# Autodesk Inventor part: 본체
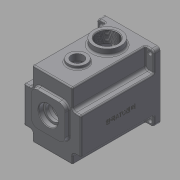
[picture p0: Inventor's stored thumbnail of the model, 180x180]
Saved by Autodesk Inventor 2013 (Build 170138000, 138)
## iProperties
Created: 2016-02
Part Number: 본체
Material: 알루미늄 6061
Document SubType Name: Modeling
Designer: mduedu
Density: 2.71 g/cm^3
Mass: 1353.73 g
Surface Area: 1142.22 cm^2
Volume: 499.53 cm^3
Author: mduedu
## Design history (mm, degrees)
sketch "스케치1"
  geometry: L1 (-47, -47)-(47, -47); L2 (47, -47)-(47, 63); L3 (47, 63)-(-47, 63); L4 (-47, 63)-(-47, -47); 2 further points
  constraints: 8 end point, 2 parallel, 1 horizontal, 1 midpoint, 1 perpendicular, 1 vertical alignment
  dimensions: "d0" = 94 distance of L2.end L3.end; "d155" = 110 distance of L1.end L2.end; "d156" = 47 distance from line of L1 point (0, 0)
extrude "돌출1" new body sketch "스케치1" distance "d2" = 130; taper "d3" = 0 deg
sketch "스케치3"
  geometry: C1 r 40 at (0, 0); 1 further point
  constraints: 1 centre point, 1 coincident
  dimensions: "d9" = 80 diameter of C1
extrude "돌출3" cut sketch "스케치3" distance "d11" = 121; taper "d12" = 0 deg
sketch "스케치4"
  geometry: C1 r 21 at (0, 11); 1 further point
  constraints: 1 centre point, 1 vertical alignment
  dimensions: "d13" = 21 radius of C1; "d15" = 11 distance of point (0, 0) C1.centre
extrude "돌출4" join sketch "스케치4" distance "d16" = 7; taper "d17" = 0 deg
sketch "스케치5"
  geometry: C1 r 15 at (0, -20); 1 further point
  constraints: 1 centre point, 1 vertical alignment
  dimensions: "d18" = 15 radius of C1; "d20" = 20 distance of point (0, 0) C1.centre
extrude "돌출5" join sketch "스케치5" distance "d21" = 7; taper "d22" = 0 deg
sketch "스케치6"
  geometry: L1 (-28, -17)-(28, -17); L2 (28, -17)-(28, 39); L3 (28, 39)-(-28, 39); L4 (-28, 39)-(-28, -17); L5 (-28, -17)-(28, 39); L6 (28, -17)-(-28, 39); C1 r 28 at (0, 11); A1 r 21 centre (0, 11) between (8.978, -7.984) and (-8.978, -7.984) reference; 1 further point
  constraints: 12 end point, 2 midpoint, 2 parallel, 2 tangent, 1 centre point, 1 coincident, 1 horizontal, 1 perpendicular
  dimensions: "d23" = 56 diameter of C1
extrude "돌출6" join sketch "스케치6" distance "d25" = 7; taper "d26" = -3 deg
hole "구멍1" diameter "d29" = 35; stored, may be unused: countersink angle "d33" = 90 deg, drill point angle "d35" = 0 deg; dims "d27" = 10, "d28" = 10, "d30" = 6, "d31" = 4, "d32" = 2, "d34" = 10
hole "구멍2" diameter "d38" = 22; stored, may be unused: countersink angle "d42" = 90 deg, drill point angle "d44" = 0 deg; dims "d36" = 10, "d37" = 10, "d39" = 6, "d40" = 4, "d41" = 2, "d43" = 7
hole "구멍3" diameter "d47" = 19; stored, may be unused: countersink angle "d51" = 90 deg, drill point angle "d53" = 0 deg; dims "d45" = 10, "d46" = 10, "d48" = 6, "d49" = 4, "d50" = 2, "d52" = 1
hole "구멍4" diameter "d56" = 32; stored, may be unused: countersink angle "d60" = 90 deg, drill point angle "d62" = 0 deg; dims "d57" = 6, "d58" = 4, "d59" = 2, "d61" = 8, "d220" = 10, "d221" = 10
hole "구멍5" diameter "d65" = 25; stored, may be unused: countersink angle "d69" = 90 deg, drill point angle "d71" = 0 deg; dims "d63" = 10, "d64" = 10, "d66" = 6, "d67" = 4, "d68" = 2, "d70" = 8
fillet "모깎기2" dims "d73" = 0.3
fillet "모깎기3" dims "d74" = 2
chamfer "모따기1" distance "d75" = 1; stored, may be unused: second distance "d76" = 2, angle "d77" = 45 deg
fillet "모깎기4" dims "d78" = 3
sketch "스케치16"
  geometry: L1 (-23, 32.726)-(23, 32.726); L2 (23, 32.726)-(23, 53); L3 (23, 53)-(-23, 53); L4 (-23, 53)-(-23, 32.726); L5 (-47, 63)-(47, 63) reference; 3 further points
  constraints: 8 end point, 2 parallel, 1 horizontal, 1 midpoint, 1 perpendicular, 1 vertical alignment, 2 other
  dimensions: "d160" = 46 distance of L2.end L3.end; "d163" = 10 distance between parallel lines of L3 L5
extrude "돌출15" cut sketch "스케치16" stored distance "d164" = 10; taper "d165" = 0 deg
fillet "모깎기5" dims "d79" = 2
fillet "모깎기15" dims "d166" = 5
sketch "스케치7"
  geometry: L1 (-23, 48)-(-23, 35.228) reference; L2 (23, 35.228)-(23, 48) reference; L3 (18, 53)-(-18, 53) reference; L4 (47, 63)-(47, -47) reference; L5 (47, -47)-(-47, -47) reference; L6 (-47, -47)-(-47, 63) reference; L7 (-47, 63)-(47, 63) reference; L8 (-26, 48)-(-26, 35.228); L9 (26, 35.228)-(26, 48); L10 (18, 56)-(-18, 56); C1 r 43 at (0, 0); A1 r 5 centre (-18, 48) between (-18, 53) and (-23, 48) reference; A2 r 5 centre (-28, 35.228) between (-24.889, 31.314) and (-23, 35.228) reference; A3 r 40 centre (0, 0) between (-24.889, 31.314) and (24.889, 31.314) reference; A4 r 5 centre (28, 35.228) between (23, 35.228) and (24.889, 31.314) reference; A5 r 5 centre (18, 48) between (23, 48) and (18, 53) reference; A6 r 8 centre (-18, 48) between (-18, 56) and (-26, 48); A7 r 2 centre (-28, 35.228) between (-26.756, 33.662) and (-26, 35.228); A8 r 43 centre (0, 0) between (-26.756, 33.662) and (26.756, 33.662); A9 r 2 centre (28, 35.228) between (26, 35.228) and (26.756, 33.662); A10 r 8 centre (18, 48) between (26, 48) and (18, 56); 1 further point
  constraints: 10 point on circle, 6 centre point, 6 end point, 1 coincident, 7 other
  dimensions: "d80" = 86 diameter of C1; "d167" = 3 distance between parallel lines of L3 L10
extrude "돌출7" cut sketch "스케치7" distance "d83" = 9; taper "d84" = 0 deg
sketch "스케치8" dims "d168" = 36
  geometry: L1 (-36, 4)-(-39.799, 4); L2 (-36, -4)-(-39.799, -4); A1 r 4 centre (-36, 0) between (-36, 4) and (-36, -4); A2 r 40 centre (0, 0) between (-24.889, 31.314) and (24.889, 31.314) reference; A3 r 40 centre (0, 0) between (-39.799, 4) and (-39.799, -4); 2 further points
  constraints: 5 point on circle, 4 end point, 2 centre point, 2 coincident, 2 horizontal alignment, 2 tangent, 1 horizontal, 1 parallel, 2 other
  dimensions: "d169" = 4 radius of A1
extrude "돌출9" join sketch "스케치8" stored distance "d89" = 9; taper "d90" = 0 deg
fillet "모깎기6" dims "d91" = 3.5
node "작업 평면1"
sketch "스케치9"
  geometry: L1 (47, 63)-(33, 63); L2 (33, 63)-(33, 30); L3 (33, 30)-(47, 30); L4 (47, 30)-(47, 63); L5 (47, 63)-(-47, 63) reference; L6 (47, -47)-(47, 63) reference; A1 r 40 centre (0, 0) between (-39.148, -8.214) and (39.148, -8.214) reference; 1 further point
  constraints: 8 end point, 2 parallel, 1 coincident, 1 horizontal, 1 perpendicular
  dimensions: "d95" = 33 distance from line of L2 point (0, 0); "d96" = 30 distance from line of L3 point (0, 0)
extrude "돌출10" cut sketch "스케치9" distance "d97" = 110; taper "d98" = 0 deg
extrude "돌출21" cut sketch "스케치9" stored distance "d217" = 10; taper "d218" = 0 deg
sketch "스케치11" dims "d20" = 20
  geometry: L1 (-40, -40)-(40, -40); L2 (40, -40)-(40, 56); L3 (40, 56)-(-40, 56); L4 (-40, 56)-(-40, -40); L5 (-47, -47)-(47, -47) reference; L6 (47, 63)-(-47, 63) reference; L7 (-47, 63)-(-47, -47) reference; C1 r 3.5 at (-40, 56); C2 r 3.5 at (40, 56); C3 r 3.5 at (40, -40); C4 r 3.5 at (-40, -40); 1 further point
  constraints: 8 end point, 4 centre point, 4 coincident, 3 equal radius, 2 parallel, 1 horizontal, 1 perpendicular
  dimensions: "d109" = 80 distance of L2.end L3.end; "d112" = 7 diameter of C1; "d157" = 7 distance from line of L1.start L5; "d158" = 7 distance between parallel lines of L6 L3; "d159" = 7 distance from line of L7 L3.end
extrude "돌출12" cut sketch "스케치11" stored distance "d113" = 63; taper "d114" = 0 deg
fillet "모깎기7" dims "d115" = 5, "d187" = 5
fillet "모깎기8" dims "d116" = 5
fillet "모깎기18" dims "d219" = 2
fillet "모깎기12" dims "d120" = 2
fillet "모깎기13" dims "d121" = 2
sketch "스케치12"
  geometry: 3 further points
  constraints: 2 horizontal alignment
hole "구멍6" sketch "스케치12" at (36, 0), (-36, 0) diameter "d122" = 3.242; stored, may be unused: countersink angle "d126" = 90 deg, drill point angle "d128" = 120 deg; dims "d123" = 7, "d124" = 4, "d125" = 2, "d127" = 9
fillet "모깎기14" dims "d147" = 10
chamfer "모따기4" distance "d151" = 1; stored, may be unused: second distance "d152" = 2, angle "d153" = 45 deg
sketch "스케치20"
  geometry: L1 (73, -12)-(73, -130) reference; L2 (84, -8)-(77, -8) reference; L3 (84, 0)-(84, -8) reference; L4 (84, 0)-(0, 0) reference; L5 (7, -8)-(0, -8) reference; L6 (11, -130)-(11, -12) reference; L7 (0, -8)-(0, 0) reference; L8 (73, -130)-(11, -130) reference; L9 (42, 0)-(42, -130); C1 r 10 at (42, -89); A1 r 4 centre (77, -12) between (77, -8) and (73, -12) reference; A2 r 4 centre (7, -12) between (11, -12) and (7, -8) reference
  constraints: 2 end point, 1 centre point, 1 midpoint, 1 point on line
  dimensions: "d189" = 20 diameter of C1; "d190" = 41 distance from line of C1.centre L8
extrude "돌출19" cut sketch "스케치20" stored distance "d191" = 10; taper "d192" = 0 deg
sketch "스케치18"
  geometry: C1 r 15 at (42, -89); C2 r 10 at (42, -89) reference; 1 further point
  constraints: 1 centre point, 1 concentric
  dimensions: "d174" = 30 diameter of C1
extrude "돌출17" join sketch "스케치18" distance "d175" = 5; taper "d176" = 0 deg
fillet "모깎기16" dims "d177" = 2
sketch "스케치19"
  geometry: C1 r 10 at (18, 80) reference; C2 r 15 at (18, 80); 1 further point
  constraints: 1 centre point, 1 coincident
  dimensions: "d178" = 30 diameter of C2
extrude "돌출18" cut sketch "스케치19" distance "d181" = 5; taper "d182" = 0 deg
chamfer "모따기5" distance "d183" = 0.5; stored, may be unused: second distance "d184" = 2, angle "d185" = 45 deg
sketch "스케치21"
  geometry: L1 (-12, 14)-(-130, 14) reference; L2 (-8, 0)-(-8, 10) reference; L3 (0, 0)-(0, 100) reference; L4 (-8, 100)-(0, 100) reference; L5 (-8, 74)-(-8, 100) reference; L6 (-130, 70)-(-12, 70) reference; L7 (-130, 14)-(-130, 70) reference; L8 (0, 0)-(-8, 0) reference; L9 (-130, 14)-(-130, 70) reference; L10 (27.4, 42)-(-164.4, 42) reference; A1 r 4 centre (-12, 74) between (-12, 70) and (-8, 74) reference; A2 r 4 centre (-12, 10) between (-8, 10) and (-12, 14) reference; 3 further points
  constraints: 1 coincident, 1 point on line, 1 other
  dimensions: "d222" = 65 distance from line of point (-65, 42) L9
feature "엠보싱2" sketch "스케치21" dims "d20" = 20, "d193" = 0.5, "d194" = 0
sketch "스케치22"
  geometry: L1 (73, -12)-(73, -130) reference; L2 (84, -8)-(77, -8) reference; L3 (84, 0)-(84, -8) reference; L4 (84, 0)-(0, 0) reference; L5 (7, -8)-(0, -8) reference; L6 (11, -130)-(11, -12) reference; L7 (0, -8)-(0, 0) reference; L8 (73, -130)-(11, -130) reference; L9 (42, -130)-(42, 0); C1 r 17 at (42, -89) reference; C2 r 22.5 at (42, -40); A1 r 4 centre (77, -12) between (77, -8) and (73, -12) reference; A2 r 4 centre (7, -12) between (11, -12) and (7, -8) reference
  constraints: 2 end point, 1 centre point, 1 midpoint, 1 point on line
  dimensions: "d195" = 45 diameter of C2; "d197" = 40 distance from line of C2.centre L4
extrude "돌출20" join sketch "스케치22" distance "d198" = 10; taper "d199" = 0 deg
fillet "모깎기17" dims "d200" = 3
hole "구멍7" diameter "d203" = 33.376; stored, may be unused: countersink angle "d207" = 90 deg, drill point angle "d209" = 118 deg; dims "d204" = 6, "d205" = 4, "d206" = 2, "d208" = 8, "d223" = 10, "d224" = 10
chamfer "모따기6" distance "d210" = 1; stored, may be unused: second distance "d211" = 2, angle "d212" = 45 deg
fillet "모깎기19" dims "d225" = 2
node "솔리드1"
pattern_circular "원형 패턴1" dims angle "d93" = 360 deg
mirror "대칭1"
mirror "대칭2"
node "투영된 루프1"
node "투영된 루프2"
node "투영된 루프3"
node "절단 모서리 투영3"
